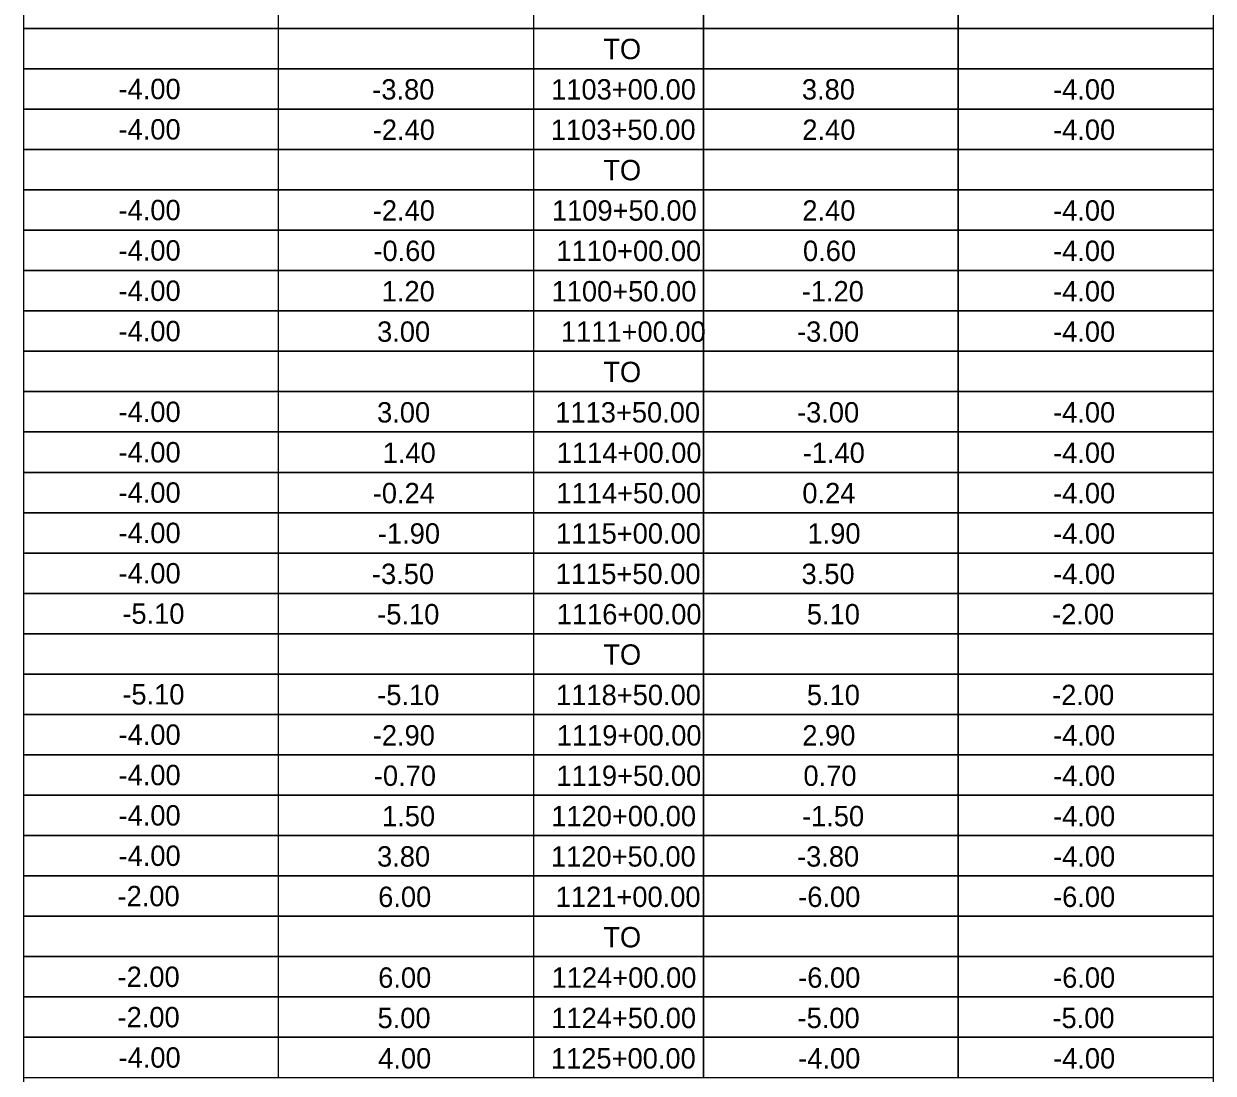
# Model space of a CAD drawing. Extents: x 1026502 to 1027102, y 781811 to 782040.
# Drawn here: x 1026688.03 to 1026716.03, y 781892.58 to 781917.29 of the extents above; entities that cross this region are included whole.
import ezdxf

# ---------------------------------------------------------------- set-up
doc = ezdxf.new("R2010")
doc.units = 0
for name, color, linetype in [('ANNOTATION', 7, 'Continuous'), ('BORDER', 7, 'Continuous'), ('DIMENSIONS', 7, 'Continuous')]:
    doc.layers.add(name, color=color, linetype=linetype)

msp = doc.modelspace()

# ---------------------------------------------------------------- linework, layer by layer
at = {"layer": 'ANNOTATION'}
msp.add_lwpolyline([(1026688.027, 781936.19), (1026716.027, 781936.19), (1026716.027, 781882.017), (1026688.027, 781882.017)], close=True, dxfattribs=at)
at = {"layer": 'BORDER'}
for p, q in [((1026691.027, 781917.182), (1026688.027, 781917.182)), ((1026691.027, 781917.182), (1026688.027, 781917.182)), ((1026691.027, 781917.182), (1026694.027, 781917.182)), ((1026691.027, 781916.231), (1026688.027, 781916.231)), ((1026691.027, 781916.231), (1026688.027, 781916.231)), ((1026691.027, 781916.231), (1026694.027, 781916.231)), ((1026691.027, 781915.281), (1026688.027, 781915.281)), ((1026691.027, 781915.281), (1026688.027, 781915.281)), ((1026691.027, 781915.281), (1026694.027, 781915.281)), ((1026691.027, 781914.33), (1026688.027, 781914.33)), ((1026691.027, 781914.33), (1026688.027, 781914.33)), ((1026691.027, 781914.33), (1026694.027, 781914.33)), ((1026691.027, 781913.38), (1026688.027, 781913.38)), ((1026691.027, 781913.38), (1026688.027, 781913.38)), ((1026691.027, 781913.38), (1026694.027, 781913.38)), ((1026691.027, 781912.43), (1026688.027, 781912.43)), ((1026691.027, 781912.43), (1026688.027, 781912.43)), ((1026691.027, 781912.43), (1026694.027, 781912.43)), ((1026691.027, 781911.479), (1026688.027, 781911.479)), ((1026691.027, 781911.479), (1026688.027, 781911.479)), ((1026691.027, 781911.479), (1026694.027, 781911.479)), ((1026691.027, 781910.529), (1026688.027, 781910.529)), ((1026691.027, 781910.529), (1026688.027, 781910.529)), ((1026691.027, 781910.529), (1026694.027, 781910.529)), ((1026691.027, 781909.578), (1026688.027, 781909.578)), ((1026691.027, 781909.578), (1026688.027, 781909.578)), ((1026691.027, 781909.578), (1026694.027, 781909.578)), ((1026691.027, 781908.628), (1026688.027, 781908.628)), ((1026691.027, 781908.628), (1026688.027, 781908.628)), ((1026691.027, 781908.628), (1026694.027, 781908.628)), ((1026691.027, 781907.678), (1026688.027, 781907.678)), ((1026691.027, 781907.678), (1026688.027, 781907.678)), ((1026691.027, 781907.678), (1026694.027, 781907.678)), ((1026691.027, 781906.727), (1026688.027, 781906.727)), ((1026691.027, 781906.727), (1026688.027, 781906.727)), ((1026691.027, 781906.727), (1026694.027, 781906.727)), ((1026691.027, 781905.777), (1026688.027, 781905.777)), ((1026691.027, 781905.777), (1026688.027, 781905.777)), ((1026691.027, 781905.777), (1026694.027, 781905.777)), ((1026691.027, 781904.826), (1026688.027, 781904.826)), ((1026691.027, 781904.826), (1026688.027, 781904.826)), ((1026691.027, 781904.826), (1026694.027, 781904.826)), ((1026691.027, 781903.876), (1026688.027, 781903.876)), ((1026691.027, 781903.876), (1026688.027, 781903.876)), ((1026691.027, 781903.876), (1026694.027, 781903.876)), ((1026691.027, 781902.926), (1026688.027, 781902.926)), ((1026691.027, 781902.926), (1026688.027, 781902.926)), ((1026691.027, 781902.926), (1026694.027, 781902.926)), ((1026691.027, 781901.975), (1026688.027, 781901.975)), ((1026691.027, 781901.975), (1026688.027, 781901.975)), ((1026691.027, 781901.975), (1026694.027, 781901.975)), ((1026691.027, 781901.025), (1026688.027, 781901.025)), ((1026691.027, 781901.025), (1026688.027, 781901.025)), ((1026691.027, 781901.025), (1026694.027, 781901.025)), ((1026691.027, 781900.074), (1026688.027, 781900.074)), ((1026691.027, 781900.074), (1026688.027, 781900.074)), ((1026691.027, 781900.074), (1026694.027, 781900.074)), ((1026691.027, 781899.124), (1026688.027, 781899.124)), ((1026691.027, 781899.124), (1026688.027, 781899.124)), ((1026691.027, 781899.124), (1026694.027, 781899.124)), ((1026691.027, 781898.174), (1026688.027, 781898.174)), ((1026691.027, 781898.174), (1026688.027, 781898.174)), ((1026691.027, 781898.174), (1026694.027, 781898.174)), ((1026691.027, 781897.223), (1026688.027, 781897.223)), ((1026691.027, 781897.223), (1026688.027, 781897.223)), ((1026691.027, 781897.223), (1026694.027, 781897.223)), ((1026691.027, 781896.273), (1026688.027, 781896.273)), ((1026691.027, 781896.273), (1026688.027, 781896.273)), ((1026691.027, 781896.273), (1026694.027, 781896.273)), ((1026691.027, 781895.322), (1026688.027, 781895.322)), ((1026691.027, 781895.322), (1026688.027, 781895.322)), ((1026691.027, 781895.322), (1026694.027, 781895.322)), ((1026691.027, 781894.372), (1026688.027, 781894.372)), ((1026691.027, 781894.372), (1026688.027, 781894.372)), ((1026691.027, 781894.372), (1026694.027, 781894.372)), ((1026691.027, 781893.422), (1026688.027, 781893.422)), ((1026691.027, 781893.422), (1026688.027, 781893.422)), ((1026691.027, 781893.422), (1026694.027, 781893.422))]:
    msp.add_line(p, q, dxfattribs=at)
for points in [[(1026688.027, 781918.132), (1026716.027, 781918.132), (1026716.027, 781917.182), (1026688.027, 781917.182)], [(1026688.027, 781917.182), (1026716.027, 781917.182), (1026716.027, 781916.231), (1026688.027, 781916.231)], [(1026688.027, 781916.231), (1026716.027, 781916.231), (1026716.027, 781915.281), (1026688.027, 781915.281)], [(1026688.027, 781915.281), (1026716.027, 781915.281), (1026716.027, 781914.33), (1026688.027, 781914.33)], [(1026688.027, 781914.33), (1026716.027, 781914.33), (1026716.027, 781913.38), (1026688.027, 781913.38)], [(1026688.027, 781913.38), (1026716.027, 781913.38), (1026716.027, 781912.43), (1026688.027, 781912.43)], [(1026688.027, 781912.43), (1026716.027, 781912.43), (1026716.027, 781911.479), (1026688.027, 781911.479)], [(1026688.027, 781911.479), (1026716.027, 781911.479), (1026716.027, 781910.529), (1026688.027, 781910.529)], [(1026688.027, 781910.529), (1026716.027, 781910.529), (1026716.027, 781909.578), (1026688.027, 781909.578)], [(1026688.027, 781909.578), (1026716.027, 781909.578), (1026716.027, 781908.628), (1026688.027, 781908.628)], [(1026688.027, 781908.628), (1026716.027, 781908.628), (1026716.027, 781907.678), (1026688.027, 781907.678)], [(1026688.027, 781907.678), (1026716.027, 781907.678), (1026716.027, 781906.727), (1026688.027, 781906.727)], [(1026688.027, 781906.727), (1026716.027, 781906.727), (1026716.027, 781905.777), (1026688.027, 781905.777)], [(1026688.027, 781905.777), (1026716.027, 781905.777), (1026716.027, 781904.826), (1026688.027, 781904.826)], [(1026688.027, 781904.826), (1026716.027, 781904.826), (1026716.027, 781903.876), (1026688.027, 781903.876)], [(1026688.027, 781903.876), (1026716.027, 781903.876), (1026716.027, 781902.926), (1026688.027, 781902.926)], [(1026688.027, 781902.926), (1026716.027, 781902.926), (1026716.027, 781901.975), (1026688.027, 781901.975)], [(1026688.027, 781901.975), (1026716.027, 781901.975), (1026716.027, 781901.025), (1026688.027, 781901.025)], [(1026688.027, 781901.025), (1026716.027, 781901.025), (1026716.027, 781900.074), (1026688.027, 781900.074)], [(1026688.027, 781900.074), (1026716.027, 781900.074), (1026716.027, 781899.124), (1026688.027, 781899.124)], [(1026688.027, 781899.124), (1026716.027, 781899.124), (1026716.027, 781898.174), (1026688.027, 781898.174)], [(1026688.027, 781898.174), (1026716.027, 781898.174), (1026716.027, 781897.223), (1026688.027, 781897.223)], [(1026688.027, 781897.223), (1026716.027, 781897.223), (1026716.027, 781896.273), (1026688.027, 781896.273)], [(1026688.027, 781896.273), (1026716.027, 781896.273), (1026716.027, 781895.322), (1026688.027, 781895.322)], [(1026688.027, 781895.322), (1026716.027, 781895.322), (1026716.027, 781894.372), (1026688.027, 781894.372)], [(1026688.027, 781894.372), (1026716.027, 781894.372), (1026716.027, 781893.422), (1026688.027, 781893.422)], [(1026688.027, 781893.422), (1026716.027, 781893.422), (1026716.027, 781892.471), (1026688.027, 781892.471)]]:
    msp.add_lwpolyline(points, close=True, dxfattribs=at)
for points in [[(1026700.027, 781918.132), (1026700.027, 781917.182), (1026694.027, 781917.182), (1026694.027, 781918.132)], [(1026704.027, 781918.132), (1026704.027, 781917.182), (1026700.027, 781917.182)], [(1026710.027, 781918.132), (1026710.027, 781917.182), (1026704.027, 781917.182), (1026704.027, 781918.132)], [(1026716.027, 781918.132), (1026716.027, 781917.182), (1026710.027, 781917.182), (1026710.027, 781918.132)], [(1026700.027, 781917.182), (1026700.027, 781916.231), (1026694.027, 781916.231), (1026694.027, 781917.182)], [(1026704.027, 781917.182), (1026704.027, 781916.231), (1026700.027, 781916.231)], [(1026710.027, 781917.182), (1026710.027, 781916.231), (1026704.027, 781916.231), (1026704.027, 781917.182)], [(1026716.027, 781917.182), (1026716.027, 781916.231), (1026710.027, 781916.231), (1026710.027, 781917.182)], [(1026700.027, 781916.231), (1026700.027, 781915.281), (1026694.027, 781915.281), (1026694.027, 781916.231)], [(1026704.027, 781916.231), (1026704.027, 781915.281), (1026700.027, 781915.281)], [(1026710.027, 781916.231), (1026710.027, 781915.281), (1026704.027, 781915.281), (1026704.027, 781916.231)], [(1026716.027, 781916.231), (1026716.027, 781915.281), (1026710.027, 781915.281), (1026710.027, 781916.231)], [(1026700.027, 781915.281), (1026700.027, 781914.33), (1026694.027, 781914.33), (1026694.027, 781915.281)], [(1026704.027, 781915.281), (1026704.027, 781914.33), (1026700.027, 781914.33)], [(1026710.027, 781915.281), (1026710.027, 781914.33), (1026704.027, 781914.33), (1026704.027, 781915.281)], [(1026716.027, 781915.281), (1026716.027, 781914.33), (1026710.027, 781914.33), (1026710.027, 781915.281)], [(1026700.027, 781914.33), (1026700.027, 781913.38), (1026694.027, 781913.38), (1026694.027, 781914.33)], [(1026704.027, 781914.33), (1026704.027, 781913.38), (1026700.027, 781913.38)], [(1026710.027, 781914.33), (1026710.027, 781913.38), (1026704.027, 781913.38), (1026704.027, 781914.33)], [(1026716.027, 781914.33), (1026716.027, 781913.38), (1026710.027, 781913.38), (1026710.027, 781914.33)], [(1026700.027, 781913.38), (1026700.027, 781912.43), (1026694.027, 781912.43), (1026694.027, 781913.38)], [(1026704.027, 781913.38), (1026704.027, 781912.43), (1026700.027, 781912.43)], [(1026710.027, 781913.38), (1026710.027, 781912.43), (1026704.027, 781912.43), (1026704.027, 781913.38)], [(1026716.027, 781913.38), (1026716.027, 781912.43), (1026710.027, 781912.43), (1026710.027, 781913.38)], [(1026700.027, 781912.43), (1026700.027, 781911.479), (1026694.027, 781911.479), (1026694.027, 781912.43)], [(1026704.027, 781912.43), (1026704.027, 781911.479), (1026700.027, 781911.479)], [(1026710.027, 781912.43), (1026710.027, 781911.479), (1026704.027, 781911.479), (1026704.027, 781912.43)], [(1026716.027, 781912.43), (1026716.027, 781911.479), (1026710.027, 781911.479), (1026710.027, 781912.43)], [(1026700.027, 781911.479), (1026700.027, 781910.529), (1026694.027, 781910.529), (1026694.027, 781911.479)], [(1026704.027, 781911.479), (1026704.027, 781910.529), (1026700.027, 781910.529)], [(1026710.027, 781911.479), (1026710.027, 781910.529), (1026704.027, 781910.529), (1026704.027, 781911.479)], [(1026716.027, 781911.479), (1026716.027, 781910.529), (1026710.027, 781910.529), (1026710.027, 781911.479)], [(1026700.027, 781910.529), (1026700.027, 781909.578), (1026694.027, 781909.578), (1026694.027, 781910.529)], [(1026704.027, 781910.529), (1026704.027, 781909.578), (1026700.027, 781909.578)], [(1026710.027, 781910.529), (1026710.027, 781909.578), (1026704.027, 781909.578), (1026704.027, 781910.529)], [(1026716.027, 781910.529), (1026716.027, 781909.578), (1026710.027, 781909.578), (1026710.027, 781910.529)], [(1026700.027, 781909.578), (1026700.027, 781908.628), (1026694.027, 781908.628), (1026694.027, 781909.578)], [(1026704.027, 781909.578), (1026704.027, 781908.628), (1026700.027, 781908.628)], [(1026710.027, 781909.578), (1026710.027, 781908.628), (1026704.027, 781908.628), (1026704.027, 781909.578)], [(1026716.027, 781909.578), (1026716.027, 781908.628), (1026710.027, 781908.628), (1026710.027, 781909.578)], [(1026700.027, 781908.628), (1026700.027, 781907.678), (1026694.027, 781907.678), (1026694.027, 781908.628)], [(1026704.027, 781908.628), (1026704.027, 781907.678), (1026700.027, 781907.678)], [(1026710.027, 781908.628), (1026710.027, 781907.678), (1026704.027, 781907.678), (1026704.027, 781908.628)], [(1026716.027, 781908.628), (1026716.027, 781907.678), (1026710.027, 781907.678), (1026710.027, 781908.628)], [(1026700.027, 781907.678), (1026700.027, 781906.727), (1026694.027, 781906.727), (1026694.027, 781907.678)], [(1026704.027, 781907.678), (1026704.027, 781906.727), (1026700.027, 781906.727)], [(1026710.027, 781907.678), (1026710.027, 781906.727), (1026704.027, 781906.727), (1026704.027, 781907.678)], [(1026716.027, 781907.678), (1026716.027, 781906.727), (1026710.027, 781906.727), (1026710.027, 781907.678)], [(1026700.027, 781906.727), (1026700.027, 781905.777), (1026694.027, 781905.777), (1026694.027, 781906.727)], [(1026704.027, 781906.727), (1026704.027, 781905.777), (1026700.027, 781905.777)], [(1026710.027, 781906.727), (1026710.027, 781905.777), (1026704.027, 781905.777), (1026704.027, 781906.727)], [(1026716.027, 781906.727), (1026716.027, 781905.777), (1026710.027, 781905.777), (1026710.027, 781906.727)], [(1026700.027, 781905.777), (1026700.027, 781904.826), (1026694.027, 781904.826), (1026694.027, 781905.777)], [(1026704.027, 781905.777), (1026704.027, 781904.826), (1026700.027, 781904.826)], [(1026710.027, 781905.777), (1026710.027, 781904.826), (1026704.027, 781904.826), (1026704.027, 781905.777)], [(1026716.027, 781905.777), (1026716.027, 781904.826), (1026710.027, 781904.826), (1026710.027, 781905.777)], [(1026700.027, 781904.826), (1026700.027, 781903.876), (1026694.027, 781903.876), (1026694.027, 781904.826)], [(1026704.027, 781904.826), (1026704.027, 781903.876), (1026700.027, 781903.876)], [(1026710.027, 781904.826), (1026710.027, 781903.876), (1026704.027, 781903.876), (1026704.027, 781904.826)], [(1026716.027, 781904.826), (1026716.027, 781903.876), (1026710.027, 781903.876), (1026710.027, 781904.826)], [(1026700.027, 781903.876), (1026700.027, 781902.926), (1026694.027, 781902.926), (1026694.027, 781903.876)], [(1026704.027, 781903.876), (1026704.027, 781902.926), (1026700.027, 781902.926)], [(1026710.027, 781903.876), (1026710.027, 781902.926), (1026704.027, 781902.926), (1026704.027, 781903.876)], [(1026716.027, 781903.876), (1026716.027, 781902.926), (1026710.027, 781902.926), (1026710.027, 781903.876)], [(1026700.027, 781902.926), (1026700.027, 781901.975), (1026694.027, 781901.975), (1026694.027, 781902.926)], [(1026704.027, 781902.926), (1026704.027, 781901.975), (1026700.027, 781901.975)], [(1026710.027, 781902.926), (1026710.027, 781901.975), (1026704.027, 781901.975), (1026704.027, 781902.926)], [(1026716.027, 781902.926), (1026716.027, 781901.975), (1026710.027, 781901.975), (1026710.027, 781902.926)], [(1026700.027, 781901.975), (1026700.027, 781901.025), (1026694.027, 781901.025), (1026694.027, 781901.975)], [(1026704.027, 781901.975), (1026704.027, 781901.025), (1026700.027, 781901.025)], [(1026710.027, 781901.975), (1026710.027, 781901.025), (1026704.027, 781901.025), (1026704.027, 781901.975)], [(1026716.027, 781901.975), (1026716.027, 781901.025), (1026710.027, 781901.025), (1026710.027, 781901.975)], [(1026700.027, 781901.025), (1026700.027, 781900.074), (1026694.027, 781900.074), (1026694.027, 781901.025)], [(1026704.027, 781901.025), (1026704.027, 781900.074), (1026700.027, 781900.074)], [(1026710.027, 781901.025), (1026710.027, 781900.074), (1026704.027, 781900.074), (1026704.027, 781901.025)], [(1026716.027, 781901.025), (1026716.027, 781900.074), (1026710.027, 781900.074), (1026710.027, 781901.025)], [(1026700.027, 781900.074), (1026700.027, 781899.124), (1026694.027, 781899.124), (1026694.027, 781900.074)], [(1026704.027, 781900.074), (1026704.027, 781899.124), (1026700.027, 781899.124)], [(1026710.027, 781900.074), (1026710.027, 781899.124), (1026704.027, 781899.124), (1026704.027, 781900.074)], [(1026716.027, 781900.074), (1026716.027, 781899.124), (1026710.027, 781899.124), (1026710.027, 781900.074)], [(1026700.027, 781899.124), (1026700.027, 781898.174), (1026694.027, 781898.174), (1026694.027, 781899.124)], [(1026704.027, 781899.124), (1026704.027, 781898.174), (1026700.027, 781898.174)], [(1026710.027, 781899.124), (1026710.027, 781898.174), (1026704.027, 781898.174), (1026704.027, 781899.124)], [(1026716.027, 781899.124), (1026716.027, 781898.174), (1026710.027, 781898.174), (1026710.027, 781899.124)], [(1026700.027, 781898.174), (1026700.027, 781897.223), (1026694.027, 781897.223), (1026694.027, 781898.174)], [(1026704.027, 781898.174), (1026704.027, 781897.223), (1026700.027, 781897.223)], [(1026710.027, 781898.174), (1026710.027, 781897.223), (1026704.027, 781897.223), (1026704.027, 781898.174)], [(1026716.027, 781898.174), (1026716.027, 781897.223), (1026710.027, 781897.223), (1026710.027, 781898.174)], [(1026700.027, 781897.223), (1026700.027, 781896.273), (1026694.027, 781896.273), (1026694.027, 781897.223)], [(1026704.027, 781897.223), (1026704.027, 781896.273), (1026700.027, 781896.273)], [(1026710.027, 781897.223), (1026710.027, 781896.273), (1026704.027, 781896.273), (1026704.027, 781897.223)], [(1026716.027, 781897.223), (1026716.027, 781896.273), (1026710.027, 781896.273), (1026710.027, 781897.223)], [(1026700.027, 781896.273), (1026700.027, 781895.322), (1026694.027, 781895.322), (1026694.027, 781896.273)], [(1026704.027, 781896.273), (1026704.027, 781895.322), (1026700.027, 781895.322)], [(1026710.027, 781896.273), (1026710.027, 781895.322), (1026704.027, 781895.322), (1026704.027, 781896.273)], [(1026716.027, 781896.273), (1026716.027, 781895.322), (1026710.027, 781895.322), (1026710.027, 781896.273)], [(1026700.027, 781895.322), (1026700.027, 781894.372), (1026694.027, 781894.372), (1026694.027, 781895.322)], [(1026704.027, 781895.322), (1026704.027, 781894.372), (1026700.027, 781894.372)], [(1026710.027, 781895.322), (1026710.027, 781894.372), (1026704.027, 781894.372), (1026704.027, 781895.322)], [(1026716.027, 781895.322), (1026716.027, 781894.372), (1026710.027, 781894.372), (1026710.027, 781895.322)], [(1026700.027, 781894.372), (1026700.027, 781893.422), (1026694.027, 781893.422), (1026694.027, 781894.372)], [(1026704.027, 781894.372), (1026704.027, 781893.422), (1026700.027, 781893.422)], [(1026710.027, 781894.372), (1026710.027, 781893.422), (1026704.027, 781893.422), (1026704.027, 781894.372)], [(1026716.027, 781894.372), (1026716.027, 781893.422), (1026710.027, 781893.422), (1026710.027, 781894.372)], [(1026700.027, 781893.422), (1026700.027, 781892.471), (1026694.027, 781892.471), (1026694.027, 781893.422)], [(1026704.027, 781893.422), (1026704.027, 781892.471), (1026700.027, 781892.471)], [(1026710.027, 781893.422), (1026710.027, 781892.471), (1026704.027, 781892.471), (1026704.027, 781893.422)], [(1026716.027, 781893.422), (1026716.027, 781892.471), (1026710.027, 781892.471), (1026710.027, 781893.422)]]:
    msp.add_lwpolyline(points, dxfattribs=at)

# ---------------------------------------------------------------- texts
at = {"layer": 'DIMENSIONS'}
for s, p in [('TO', (1026701.669, 781916.458)), ('-4.00', (1026690.257, 781915.516)), ('-3.80', (1026696.23, 781915.507)), ('1103+00.00', (1026700.441, 781915.507)), ('3.80', (1026706.344, 781915.507)), ('-4.00', (1026712.257, 781915.507)), ('-4.00', (1026690.257, 781914.566)), ('-2.40', (1026696.242, 781914.557)), ('1103+50.00', (1026700.433, 781914.557)), ('2.40', (1026706.355, 781914.557)), ('-4.00', (1026712.257, 781914.557)), ('TO', (1026701.669, 781913.606)), ('-4.00', (1026690.257, 781912.665)), ('-2.40', (1026696.242, 781912.655)), ('1109+50.00', (1026700.46, 781912.655)), ('2.40', (1026706.355, 781912.655)), ('-4.00', (1026712.257, 781912.655)), ('-4.00', (1026690.257, 781911.714)), ('-0.60', (1026696.257, 781911.704)), ('1110+00.00', (1026700.565, 781911.704)), ('0.60', (1026706.37, 781911.704)), ('-4.00', (1026712.257, 781911.704)), ('-4.00', (1026690.257, 781910.764)), ('1.20', (1026696.453, 781910.753)), ('1100+50.00', (1026700.452, 781910.753)), ('-1.20', (1026706.34, 781910.753)), ('-4.00', (1026712.257, 781910.753)), ('-4.00', (1026690.257, 781909.814)), ('3.00', (1026696.344, 781909.802)), ('1111+00.00', (1026700.671, 781909.802)), ('-3.00', (1026706.23, 781909.802)), ('-4.00', (1026712.257, 781909.802)), ('TO', (1026701.669, 781908.852)), ('-4.00', (1026690.257, 781907.913)), ('3.00', (1026696.344, 781907.901)), ('1113+50.00', (1026700.539, 781907.901)), ('-3.00', (1026706.23, 781907.901)), ('-4.00', (1026712.257, 781907.901)), ('-4.00', (1026690.257, 781906.962)), ('1.40', (1026696.476, 781906.95)), ('1114+00.00', (1026700.573, 781906.95)), ('-1.40', (1026706.363, 781906.95)), ('-4.00', (1026712.257, 781906.95)), ('-4.00', (1026690.257, 781906.012)), ('-0.24', (1026696.242, 781905.999)), ('1114+50.00', (1026700.565, 781905.999)), ('0.24', (1026706.355, 781905.999)), ('-4.00', (1026712.257, 781905.999)), ('-4.00', (1026690.257, 781905.062)), ('-1.90', (1026696.363, 781905.048)), ('1115+00.00', (1026700.558, 781905.048)), ('1.90', (1026706.476, 781905.048)), ('-4.00', (1026712.257, 781905.048)), ('-4.00', (1026690.257, 781904.111)), ('-3.50', (1026696.223, 781904.097)), ('1115+50.00', (1026700.55, 781904.097)), ('3.50', (1026706.336, 781904.097)), ('-4.00', (1026712.257, 781904.097)), ('-5.10', (1026690.347, 781903.161)), ('-5.10', (1026696.347, 781903.147)), ('1116+00.00', (1026700.573, 781903.147)), ('5.10', (1026706.461, 781903.147)), ('-2.00', (1026712.234, 781903.147)), ('TO', (1026701.669, 781902.196)), ('-5.10', (1026690.347, 781901.26)), ('-5.10', (1026696.347, 781901.245)), ('1118+50.00', (1026700.558, 781901.245)), ('5.10', (1026706.461, 781901.245)), ('-2.00', (1026712.234, 781901.245)), ('-4.00', (1026690.257, 781900.31)), ('-2.90', (1026696.242, 781900.294)), ('1119+00.00', (1026700.573, 781900.294)), ('2.90', (1026706.355, 781900.294)), ('-4.00', (1026712.257, 781900.294)), ('-4.00', (1026690.257, 781899.359)), ('-0.70', (1026696.268, 781899.343)), ('1119+50.00', (1026700.565, 781899.343)), ('0.70', (1026706.381, 781899.343)), ('-4.00', (1026712.257, 781899.343)), ('-4.00', (1026690.257, 781898.409)), ('1.50', (1026696.461, 781898.392)), ('1120+00.00', (1026700.444, 781898.392)), ('-1.50', (1026706.347, 781898.392)), ('-4.00', (1026712.257, 781898.392)), ('-4.00', (1026690.257, 781897.458)), ('3.80', (1026696.344, 781897.442)), ('1120+50.00', (1026700.437, 781897.442)), ('-3.80', (1026706.23, 781897.442)), ('-4.00', (1026712.257, 781897.442)), ('-2.00', (1026690.234, 781896.508)), ('6.00', (1026696.37, 781896.491)), ('1121+00.00', (1026700.55, 781896.491)), ('-6.00', (1026706.257, 781896.491)), ('-6.00', (1026712.257, 781896.491)), ('TO', (1026701.669, 781895.54)), ('-2.00', (1026690.234, 781894.607)), ('6.00', (1026696.37, 781894.589)), ('1124+00.00', (1026700.452, 781894.589)), ('-6.00', (1026706.257, 781894.589)), ('-6.00', (1026712.257, 781894.589)), ('-2.00', (1026690.234, 781893.657)), ('5.00', (1026696.355, 781893.638)), ('1124+50.00', (1026700.444, 781893.638)), ('-5.00', (1026706.242, 781893.638)), ('-5.00', (1026712.242, 781893.638)), ('-4.00', (1026690.257, 781892.706)), ('4.00', (1026696.37, 781892.687)), ('1125+00.00', (1026700.437, 781892.687)), ('-4.00', (1026706.257, 781892.687)), ('-4.00', (1026712.257, 781892.687))]:
    msp.add_text(s, height=0.48, dxfattribs=at).set_placement(p)

doc.saveas('drawing.dxf')
